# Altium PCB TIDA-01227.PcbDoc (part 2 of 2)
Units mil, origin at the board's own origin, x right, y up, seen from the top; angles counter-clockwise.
Board outline 2300 x 2250 mil, 2 copper layers (Top Layer, Bottom Layer), stack 64.8 mil thick; 107 components, 78 nets, 446 pads, 341 vias.
Unrouted connection lines stored in the file: 1.
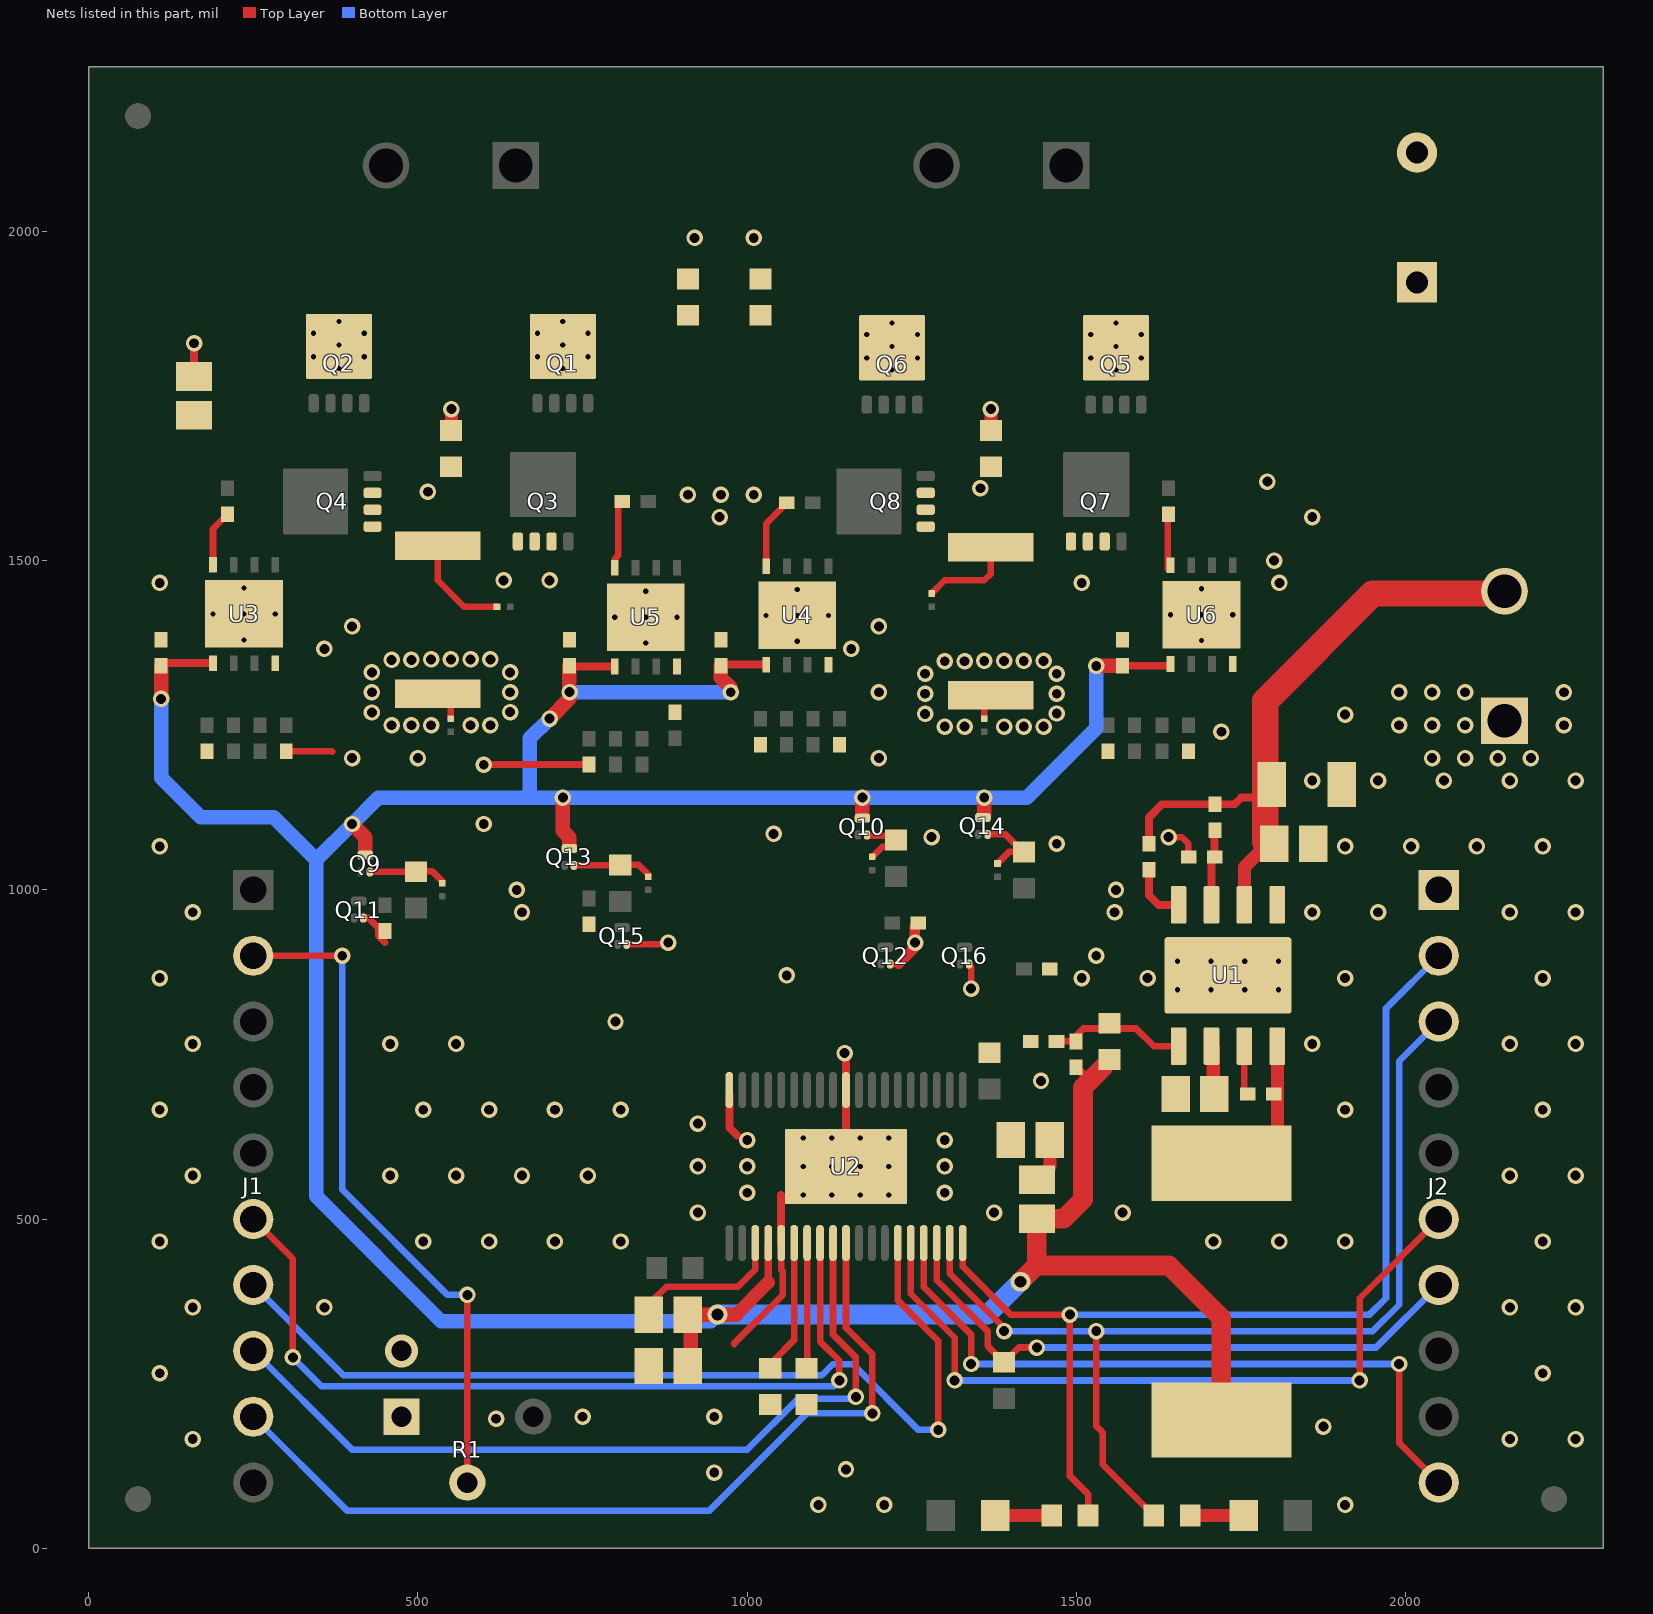
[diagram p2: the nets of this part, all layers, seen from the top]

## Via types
v1: diameter 25, hole 15, Top Layer to Bottom Layer, tented both sides, 241 vias
v2: diameter 19.68, hole 7.87, Top Layer to Bottom Layer, 92 vias
v3: diameter 19.68, hole 7.87, Top Layer to Bottom Layer, tented both sides, 4 vias
v4: diameter 50, hole 31, Top Layer to Bottom Layer, tented both sides, 2 vias
v5: diameter 30, hole 18, Top Layer to Bottom Layer, tented both sides, 2 vias

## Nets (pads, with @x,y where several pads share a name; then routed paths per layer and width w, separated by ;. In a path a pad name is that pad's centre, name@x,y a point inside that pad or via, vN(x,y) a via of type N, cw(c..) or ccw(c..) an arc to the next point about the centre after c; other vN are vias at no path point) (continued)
GND: C1.2 C2.2 C5.2 C6.2 C8.2 C9.2 C10.2 C11.2 C14.2 C17.2 C18.2 C21.2 C22.2 C23.2 C24.2 C25.2 C26.2 J2.1 J4.1 NT2.2 NT4.1 Q11.2 Q12.2 Q15.2 Q16.2 R1.1 R5.1 R6.1 R7.1 R9.1 R12.1 R15.1 R17.1 R19.1 R20.1 R23.1 R24.1 R27.1 R29.1 R31.1 R32.1 R35.1 R36.1 U1.1 U1.9@1730,870 U2.5 U2.29 U2.38 U2.39 U3.4 U3.9 U4.4 U4.9 U5.4 U5.9 U6.4 U6.9 | length 1083.4
  Top Layer w10: R23.1@300,1210.32 369.68,1210.32 370,1210 ; Q11.2@421,957.2 424.86,957.2 440,942.06 440,930 450,920 ; R9.1@530,1297.8 550,1277.8 NT2.2@550,1260 ; v1(600,1190) 600.32,1190.32 R27.1@760,1190.32 ; Q15.2@821,917.2 877.2,917.2 v1(880,920) ; 980,310 980,311.11 1053.89,385 1053.89,421 1051.57,423.32 U2.5@1051.57,463.86 ; v1(1148,752) v1@1150,750 ; 1223,887 1231.49,887 ; v1(1340,850) 1336.89,853.11 1340,856.22 Q16.2@1340,882.12 ; NT4.1@1360,1260 1360,1285.59 R12.1@1370,1295.59 ; v1(1640,1080) 1660,1080 1670,1070 1670,1050.32 R5.1@1670.32,1050
  Top Layer w12: U2.38@972.83,689.25 972.83,639.06 984.65,627.24 ; U2.5@1051.57,463.86 1051.57,536.43 ; U2.39@1150,580 U2.29@1150,689.25 ; U2.29@1150,696.14 v1@1150,750
  Top Layer w16: 1230,887.82 1254.68,912.51 R20.1@1254.68,945
  other v1: 1108,66 1208,66 1908,66 950,115 1150,120 158,166 2158,166 2258,166 1875,185 618.69,196.95 750,200 950,200 108,266 2208,266 158,366 358,366 2158,366 2258,366 108,466 508,466 608,466 708,466 808,466 1708,466 1808,466 1908,466 2208,466 925,510 1375,510 1570,510 1000,540 1300,540 158,566 458,566 558,566 658,566 758,566 2158,566 2258,566 925,580 1000,580 1300,580 1000,620 1300,620 925,645 108,666 508,666 608,666 708,666 808,666 1908,666 2208,666 1446.1,710 158,766 458,766 558,766 1858,766 2158,766 2258,766 800,800 108,866 1508,866 1608,866 1908,866 2208,866 1060,870 1530,900 1255,920 158,966 658,966 1558,966 1858,966 1958,966 2158,966 2258,966 650,1000 1560,1000 108,1066 1908,1066 2008,1066 2108,1066 2208,1066 1470,1070 1280,1080 1040,1085 600,1100 1858,1166 1958,1166 2058,1166 2158,1166 2258,1166 400,1200 500,1200 1200,1200 2040,1200 2090,1200 2140,1200 2190,1200 1720,1240 1300,1247.8 1330,1247.8 1390,1247.8 1420,1247.8 1450,1247.8 460,1250 490,1250 520,1250 580,1250 610,1250 1990,1250 2040,1250 2090,1250 2240,1250 1908,1266 1270,1267.11 1470,1267.8 430,1269.32 640,1270 1270,1297.8 1470,1297.8 430,1300 640,1300 1200,1300 1990,1300 2040,1300 2090,1300 2240,1300 1270,1328.11 1470,1328.11 430,1330.32 640,1330.32 1300,1347.09 1330,1347.09 1360,1347.8 1390,1347.8 1420,1347.8 1450,1347.8 460,1349.29 490,1349.29 520,1350 550,1350 580,1350 610,1350 358,1366 1158,1366 400,1400 1200,1400 108,1466 1508,1466 1808,1466 630,1470 700,1470 1800,1500 958,1566 1858,1566 910,1600 960,1600 1010,1600 514.98,1604.55 1354.08,1609.76 1790,1620
  other v2: 1085.04,536.69 1128.35,536.69 1171.65,536.69 1214.96,536.69 1085.04,580 1128.35,580 1171.65,580 1214.96,580 1085.04,623.31 1128.35,623.31 1171.65,623.31 1214.96,623.31 1704.41,848.35 1755.59,848.35 1704.41,891.65 1755.59,891.65 846,1374.63 1076,1377.43 1690,1378.43 236,1379.63 798.76,1414 846,1414 893.24,1414 1028.76,1416.8 1076,1416.8 1123.24,1416.8 1642.76,1417.8 1690,1417.8 1737.24,1417.8 188.76,1419 236,1419 283.24,1419 846,1453.37 1076,1456.17 1690,1457.17 236,1458.37
  other v3: 1653.23,848.35 1806.77,848.35 1653.23,891.65 1806.77,891.65
  other v4: 475,300
GND_A: NT1.2 Q3.1 Q3.2 Q3.3 Q4.1 Q4.2 Q4.3 R9.2 | length 158.8
  Top Layer w10: R9.2@530,1522.2 530,1470 570,1430 NT1.2@620,1430
GND_B: NT3.1 Q7.1 Q7.2 Q7.3 Q8.1 Q8.2 Q8.3 R12.2 | length 142.4
  Top Layer w10: NT3.1@1280,1450 1300,1470 1360,1470 1370,1480 R12.2@1370,1520
NetC3_1: C3.1 U1.7 | length 74.9
  Top Layer w10: U1.7@1755,762.72 1755,695.32 C3.1@1760.32,690
NetC3_2: C3.2 L1.1 U1.8 | length 144.9
  Top Layer w20: L1.1@1720,584.88 L1.1@1724.88,584.88 ; L1.1@1805,620 U1.8@1805,760
NetC4_2: C4.2 R4.1 R6.2 U1.5 | length 209.7
  Top Layer w10: R6.2@1469.69,770 1498.68,770 R4.1@1499,769.68 1499,778.05 1510.47,789.53 1590.47,789.53 1617.28,762.72 U1.5@1655,762.72
NetC7_2: C7.2 R7.2 | length 78.6
  Top Layer w20: C7.2@1440,559.53 1459.53,579.05 R7.2@1459.53,630
NetC8_1: C8.1 U1.6 | length 73.8
  Top Layer w20: U1.6@1705,762.72 1707.56,760.16 C8.1@1707.56,690
NetC15_2: C15.2 U3.8 | length 85.8
  Top Layer w10: U3.8@188.76,1493.8 188.76,1548.41 188.93,1548.41 C15.2@210.84,1570.31
NetC16_2: C16.2 U4.8 | length 109.3
  Top Layer w10: U4.8@1028.76,1491.6 1028.76,1556.24 C16.2@1060.31,1587.8
NetC19_2: C19.2 U5.8 | length 106
  Top Layer w10: U5.8@798.76,1488.8 798.76,1502.58 804,1507.83 804,1583.69 C19.2@810.31,1590
NetC20_2: C20.2 U6.8 | length 89.6
  Top Layer w10: U6.8@1638.76,1486.6 C20.2@1638.76,1576.24
NetD1_1: D1.1 R11.2 | length 86.1
  Top Layer w20: D1.1@1376.34,50 R11.2@1462.44,50
NetD2_1: D2.1 R10.1 | length 81.1
  Top Layer w20: R10.1@1672.56,50 D2.1@1753.66,50
NetNT5_2: NT5.2 Q9.2 R16.2 | length 114.7
  Top Layer w10: 432,1027.2 496.85,1027.2 R16.2@497.2,1027.56 497.7,1028.05 521.95,1028.05 537.2,1012.8 NT5.2@537.2,1010
NetNT6_2: NT6.2 Q10.2 R18.2 | length 79.6
  Top Layer w10: 1187,1082 R18.2@1220,1082 ; NT6.2@1190,1050 1205.33,1065.33 1215.77,1065.33 R18.2@1226,1075.56
NetNT7_2: NT7.2 Q13.2 R28.2 | length 113.5
  Top Layer w10: 742,1037.21 R28.2@809.65,1037.2 ; R28.2@810.49,1038.05 834.74,1038.05 NT7.2@850,1022.8
NetNT8_2: NT8.2 Q14.2 R30.2 | length 108.3
  Top Layer w10: Q14.2@1369,1084.2 1392.37,1084.2 R30.2@1419.02,1057.56 ; NT8.2@1380,1040 1397.56,1057.56 R30.2@1419.02,1057.56 ; R30.2@1420,1057.56 R30.2@1419.02,1057.56
NetR2_2: R2.2 U1.4 | length 76
  Top Layer w12: R2.2@1610,1030.31 1610,991.73 1624.45,977.28 1641.46,977.28
NetR3_1: R3.1 R5.2 U1.3 | length 104.3
  Top Layer w12: U1.3@1705,977.28 1705,1045.31 R5.2@1709.69,1050 1709.69,1078.82 R3.1@1709.1,1079.41
NFAULT: J2.3 R10.2 U2.18 | length 1562.6
  Top Layer w10: U2.18@1307.48,470.75 1307.48,417.52 1390,335 v1(1390,330) ; v1(1530,330) 1530,185.84 1540,175.84 1540,127.44 R10.2@1617.44,50
  Bottom Layer w10: v1(1390,330) 1950,330 1990,370 1990,740 J2.3@2050,800
NSLEEP: J1.6 U2.8 | length 1314.7
  Top Layer w10: J1.6@250,500 310,440 v1(310,290) ; U2.8@1110.63,470.75 1110.63,314.37 1140,285 v1(1140,255)
  Bottom Layer w10: v1(310,290) 354,246 1131,246 v1(1140,255)
NSTALL: J2.2 R11.1 U2.19 | length 1595.8
  Top Layer w10: U2.19@1327.17,470.75 1327.17,427.83 1400,355 v1(1490,355) 1490,110 1517.56,82.44 R11.1@1517.56,50
  Bottom Layer w10: v1(1490,355) 1945,355 1970,380 1970,820 J2.2@2050,900
POT: J1.2 R1.2 | length 1011.3
  Top Layer w10: J1.2@250,900 v1@375,900 ; R1.2@575,100 v1@575,375
  Bottom Layer w10: v1(385,900) 385,544.92 544.92,385 v1(575,385)
RESET: J1.8 U2.9 | length 1270.4
  Top Layer w10: U2.9@1130.31,475.75 1130.31,324.69 1165,290 v1(1165,230)
  Bottom Layer w10: J1.8@250,300 400,150 1000.11,150 1077.11,227 1162,227 v1(1165,230)
SCLK: J1.7 U2.14 | length 1460.9
  Top Layer w10: U2.14@1228.74,470.75 1228.74,376.26 1290,315 v1(1290,180)
  Bottom Layer w10: J1.7@250,400 387,263 1113.35,263 1129.85,279.5 1160.5,279.5 1260,180 v1(1290,180)
SCS: J2.10 U2.16 | length 1070.4
  Top Layer w10: U2.16@1268.11,470.75 1268.11,396.89 1340,325 v1@1340,285 ; v1(1990,280) 1990,160 J2.10@2050,100
  Bottom Layer w10: v1(1340,280) v1(1990,280)
SDATI: J2.6 U2.15 | length 1153
  Top Layer w10: U2.15@1248.43,470.75 1248.43,386.57 1315,320 v1(1315,255) ; v1(1930,255) 1930,380 J2.6@2050,500
  Bottom Layer w10: v1(1315,255) v1(1930,255)
SDATO: J2.7 R8.1 U2.17 | length 939.2
  Top Layer w10: U2.17@1287.8,470.75 1287.8,407.2 1365,330 1365,307.56 R8.1@1390,282.56 1412.44,305 v1(1440,305)
  Bottom Layer w10: v1(1440,305) 1780,305 1955,305 J2.7@2050,400
STEP/AIN1: J1.9 U2.10 | length 1342.9
  Top Layer w10: U2.10@1150,470.75 1150,335 1190,295 v1(1190,205)
  Bottom Layer w10: J1.9@250,200 393,57 942,57 1090,205 v1(1190,205)
V5: C10.1 U2.6 | length 211.7
  Top Layer w10: C10.1@1041,271.56 1041,286 1071.26,316.26 U2.6@1071.26,463.86 U2.6@1071.26,470.75
V12: C4.1 C7.1 C9.1 C13.2 C17.1 C18.1 C21.1 C22.1 L1.2 Q9.3 Q10.3 Q13.3 Q14.3 R4.2 U2.4 U3.1 U4.1 U5.1 U6.1 | length 5704
  Top Layer w12: C17.1@110,1340.32 113.88,1344.2 U3.1@188.76,1344.2 ; C21.1@730,1340.32 731.12,1339.2 U5.1@798.76,1339.2 ; C18.1@960,1340.32 961.68,1341.99 U4.1@1028.76,1341.99 ; 1031.89,403.89 U2.4@1031.89,463.86 ; R4.2@1500,730.31 1519.84,710.47 1520.47,710.47 ; C22.1@1570,1340.32 1640.08,1340.32 U6.1@1642.76,1342.99
  Top Layer w20: 983,355 1031.89,403.89
  Top Layer w22: v1(110,1290) C17.1@110,1340.32 ; v1(400,1100) 420,1080 419.99,1059.69 ; v1(700,1260) 730,1290 C21.1@730,1340.32 ; v1(720,1140) 720,1090 729.99,1080.01 729.99,1069.7 ; C9.1@918.15,275 914.53,278.62 914.53,355 v5(955,355) 983,355 ; C18.1@960,1340.32 960,1321.72 975,1306.72 v1(975,1300) ; Q10.3@1175,1114.41 v1(1175,1140) ; Q14.3@1360,1114.41 v1(1360,1140) ; v1(1530,1340) 1569.68,1340 C22.1@1570,1340.32
  Top Layer w30: v5(1415,405) 1439.53,429.53 ; C4.1@1540.47,730.47 1520.47,710.47 1510,700 1510,530 1480.47,500.47 C7.1@1440,500.47 1439.53,500 1439.53,429.53 ; L1.2@1720,195.12 1720,350 1640.47,429.53 1439.53,429.53
  Bottom Layer w22: v1(110,1290) 110,1170 170,1110 281,1110 345.5,1045.5 ; v1(700,1260) 670,1230 670,1140 ; v1(730.19,1300.19) 730.39,1300 v1(975,1300) ; v5(955,355) 945,345 535,345 345.5,534.5 345.5,1045.5 ; v1(1530,1340) 1530,1245.65 1424.35,1140 v1(1360,1140) v1(1175,1140) v1(720,1140) 670,1140 ; 345.5,1045.5 v1(400,1100) 440,1140 670,1140
  Bottom Layer w30: v5(955,355) 1365,355 v5(1415,405)
VCP: C13.1 U2.3 | length 244.5
  Top Layer w10: C13.1@855.47,355 855.47,375.47 877.27,397.27 986.16,397.27 1012.2,423.32 U2.3@1012.2,463.86 U2.3@1012.2,470.75
VINT: C11.1 U2.7 | length 197.2
  Top Layer w10: C11.1@1090.94,273.5 U2.7@1090.94,470.75
VM: C1.1 C2.1 C5.1 C6.1 C23.1 C24.1 C25.1 C26.1 J4.2 Q1.5 Q1.6 Q1.7 Q1.8 Q1.9@720,1825.39 Q2.5 Q2.6 Q2.7 Q2.8 Q2.9@380,1825.39 Q5.5 Q5.6 Q5.7 Q5.8 Q5.9@1560,1823.19 Q6.5 Q6.6 Q6.7 Q6.8 Q6.9@1220,1823.19 R2.1 R3.2 U1.2 | length 1102.4
  Top Layer w12: C2.1@160,1777.56 v1@160,1820 ; R2.1@1610,1069.68 1610,1110 1630,1130 1740,1130 1750,1140 1766.85,1140 C5.1@1786.85,1160
  Top Layer w20: C24.1@550.73,1698.29 v1(550.73,1730) ; C26.1@1370,1697.56 v1(1370,1730) ; U1.2@1755,977.28 1755,1034.53 C6.1@1790.47,1070
  Top Layer w40: C6.1@1790.47,1070 1786.85,1073.62 1786.85,1160 1786.85,1286.85 1950,1450 2146.57,1450 J4.2@2150,1453.43
  other v1: 160,1830 920,1990 1010,1990
  other v2: 1220,1789.63 1560,1789.63 380,1791.83 720,1791.83 1181.61,1807.44 1258.39,1807.44 1521.61,1807.44 1598.39,1807.44 341.61,1809.65 418.39,1809.65 681.61,1809.65 758.39,1809.65 1220,1825.26 1560,1825.26 380,1827.46 720,1827.46 1181.61,1843.07 1258.39,1843.07 1521.61,1843.07 1598.39,1843.07 341.61,1845.28 418.39,1845.28 681.61,1845.28 758.39,1845.28 1220,1860.89 1560,1860.89 380,1863.09 720,1863.09
pads on no net: FID1.1 FID2.1 FID3.1 J1.3 J1.4 J1.5 J2.4 J2.5 Q1.9@681.61,1846.26 Q1.9@693.92,1791.83 Q1.9@693.92,1827.46 Q1.9@707.2,1846.26 Q1.9@720,1812.89 Q1.9@732.8,1846.26 Q1.9@746.08,1791.83 Q1.9@746.08,1827.46 Q1.9@758.39,1846.26 Q2.9@341.61,1846.26 Q2.9@353.92,1791.83 Q2.9@353.92,1827.46 Q2.9@367.2,1846.26 Q2.9@380,1812.89 Q2.9@392.8,1846.26 Q2.9@406.08,1791.83 Q2.9@406.08,1827.46 Q2.9@418.39,1846.26 Q3.9@651.61,1636.26 Q3.9@663.92,1581.83 Q3.9@663.92,1617.46 Q3.9@677.2,1636.26 Q3.9@690,1602.89 Q3.9@702.8,1636.26 Q3.9@716.08,1581.83 Q3.9@716.08,1617.46 Q3.9@728.39,1636.26 Q4.9@323.74,1551.61 Q4.9@323.74,1577.2 Q4.9@323.74,1602.8 Q4.9@323.74,1628.39 Q4.9@342.54,1563.92 Q4.9@342.54,1616.08 Q4.9@357.11,1590 Q4.9@378.17,1563.92 Q4.9@378.17,1616.08 Q5.9@1521.61,1844.06 Q5.9@1533.92,1789.63 Q5.9@1533.92,1825.26 Q5.9@1547.2,1844.06 Q5.9@1560,1810.69 Q5.9@1572.8,1844.06 Q5.9@1586.08,1789.63 Q5.9@1586.08,1825.26 Q5.9@1598.39,1844.06 Q6.9@1181.61,1844.06 Q6.9@1193.92,1789.63 Q6.9@1193.92,1825.26 Q6.9@1207.2,1844.06 Q6.9@1220,1810.69 Q6.9@1232.8,1844.06 Q6.9@1246.08,1789.63 Q6.9@1246.08,1825.26 Q6.9@1258.39,1844.06 Q7.9@1491.61,1636.26 Q7.9@1503.92,1581.83 Q7.9@1503.92,1617.46 Q7.9@1517.2,1636.26 Q7.9@1530,1602.89 Q7.9@1542.8,1636.26 Q7.9@1556.08,1581.83 Q7.9@1556.08,1617.46 Q7.9@1568.39,1636.26 Q8.9@1163.74,1551.61 Q8.9@1163.74,1577.2 Q8.9@1163.74,1602.8 Q8.9@1163.74,1628.39 Q8.9@1182.54,1563.92 Q8.9@1182.54,1616.08 Q8.9@1197.11,1590 Q8.9@1218.17,1563.92 Q8.9@1218.17,1616.08 Q9.0 Q10.0 Q11.0 Q12.0 Q13.0 Q14.0 Q15.0 Q16.0 U1.9@1730,870

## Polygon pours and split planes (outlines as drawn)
GND on Bottom Layer "GND_BOT" (solid, remove dead copper, pour order 39): 0,2234.46 2300,2234.46 2300,-15.54 0,-15.54
VM on Bottom Layer "VM_BOT" (solid, remove dead copper, pour order 38): 15.49,2250 15.49,1680 425,1680 1920,1680 1920,1365 1935,1365 2300,1365 2300,2250
GND on Top Layer "GND_TOP" (solid, remove dead copper, pour order 40): 0,2250 2300,2250 2300,0 0,0
AOUT1_MOT on Top Layer "Top Layer-AOUT1_MOT" (solid, remove dead copper, pour order 30): 220,2250 220,1532.8 530,1532.8 530,2250
AOUT2_MOT on Top Layer "Top Layer-AOUT2_MOT" (solid, remove dead copper, pour order 31): 560,2250 560,1560 870,1560 870,2250
BOUT2_MOT on Top Layer "Top Layer-BOUT2_MOT1" (solid, remove dead copper, pour order 32): 1400,2250 1400,1560 1710,1560 1710,2250
BOUT1_MOT on Top Layer "Top Layer-BOUT1_MOT" (solid, remove dead copper, pour order 37): 1060,2250 1060,1532.79 1370,1532.8 1370,2250

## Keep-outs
Keep-Out Layer:
  lines w20: -10,0 ccw(c0,0) 0,-10 ; -10,0 ccw(c0,0) 0,-10 ; -10,0 -10,2250 ; -10,2250 cw(c0,2250) 0,2260 ; -10,2250 cw(c0,2250) 0,2260 ; 0,-10 2300,-10 ; 0,2260 2300,2260 ; 2300,-10 ccw(c2300,0) 2310,0 ; 2300,-10 ccw(c2300,0) 2310,0 ; 2300,2260 cw(c2300,2250) 2310,2250 ; 2300,2260 cw(c2300,2250) 2310,2250 ; 2310,0 2310,2250
  text ".Layer_Name" at 577,-858.49 h60

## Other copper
Top Layer:
  rectangle net VM: 900,1920 1030,2010
  region net GND: 566.26,1657.81 566.19,1657.88 503.31,1657.88 494.25,1648.82 494.25,1590.81
  region net GND: 950.94,731.62 972.83,731.62 972.83,646.89 950.94,646.89
  region net GND_A: 710,1550 710,1500 420,1500 420,1610 440,1610 500,1550
  region net GND_B: 1550,1547.8 1550,1497.8 1260,1497.8 1260,1607.8 1280,1607.8 1340,1547.8
  region net GND: 1440,810 1440,750 1460,730 1430,730 1430,810
  text ".Layer_Name" at 577,-858.49 h60
Bottom Layer:
  text ".Layer_Name" at 577,-858.49 h60

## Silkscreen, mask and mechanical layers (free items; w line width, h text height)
Top Overlay:
  lines w7: 1840,1367 1920,1367 ; 1840,1260 1920,1260 1920,1477 1840,1477 1840,1260
  lines w10: 230,1550 230,1960 310,1960 ; 380,1500 450,1500 ; 610,1500 740,1500 ; 770,1960 1150,1960 ; 950,1500 970,1500 ; 1180,1500 1290,1500 ; 1450,1500 1550,1500 ; 1600,1960 1720,1960 1720,1550
  text ".PRJ_Number" at 790,2180 h30
  text "Rev." at 790,2130 h30
  text ".PCB_Rev" at 930,2130 h30
  text "High Voltage Stepper" at 780,1980 h30
  text "A1" at 254,1900 h40
  text "A2" at 789,1900 h40
  text "B1" at 1100,1900 h40
  text "B2" at 1630,1900 h40
  text "VM" at 1860,1457 h30 r270
  text "GND" at 1860,1357 h30 r270
  text "GND-STL-FLT" at 1955,1050 h28 r270
  text "3.3-POT" at 319.51,1047.48 h28 r270
  text "DRV8711" at 660,760 h60
  text "SLP-CLK-RST-STP-DIR" at 320,555 h28 r270
  text "SDI-SDO-B1-B2-SCS" at 2115,525 h28 r270
  text "STALL" at 1230,100 h30
  text "FAULT" at 1710,100 h30
  text ".Layer_Name" at 577,-858.49 h60
Bottom Overlay:
  text ".Layer_Name" at 577,-858.49 h60
Top Paste:
  text ".Layer_Name" at 577,-858.49 h60
Bottom Paste:
  text ".Layer_Name" at 577,-858.49 h60
Top Solder:
  text ".Layer_Name" at 577,-858.49 h60
  text ".Layer_Name" at 577,-858.49 h60
Bottom Solder:
  text ".Layer_Name" at 577,-858.49 h60
Drill Guide:
  text ".Layer_Name" at 577,-858.49 h60
M1 Board Outline:
  the board outline again, w10
  text ".Layer_Name" at 577,-858.49 h60
M2 Board Dimensions:
  rectangle: -0.5,-285.5 124.5,-160.5
  rectangle: 124.5,-410.5 499.5,-285.5
  lines w7: -0.5,-285.5 999.5,-285.5 ; 124.5,-410.5 124.5,-160.5 ; 249.5,-410.5 249.5,-160.5 ; 499.5,-410.5 499.5,-160.5 ; 749.5,-410.5 749.5,-160.5 ; -0.5,-410.5 999.5,-410.5 999.5,-160.5 -0.5,-160.5 -0.5,-410.5
  lines w10: -0.5,-475.5 -0.5,-455.5 ; 59.5,-485.5 -0.5,-465.5 ; 59.5,-445.5 -0.5,-465.5 ; 223.58,-465.5 -0.5,-465.5 ; 775.42,-465.5 999.5,-465.5 ; 939.5,-485.5 999.5,-465.5 ; 939.5,-445.5 999.5,-465.5 ; 999.5,-475.5 999.5,-455.5
  text "1000 (mil)" at 233.58,-501.49 h60
  text ".Layer_Name" at 577,-858.49 h60
M3 3D STEP Top:
  text ".Layer_Name" at 577,-858.49 h60
M4 3D STEP Bottom:
  text ".Layer_Name" at 577,-858.49 h60
M5 Assembly Top:
  lines w10: -292,-930.17 6308,-930.17 ; -292,-726.83 6310,-726.83 ; -292,-523.5 -292,-1133.5 3713,-1133.5 6310,-1133.5 6310,-523.5 -291.5,-523.5 -291.5,-1133.5 1284,-1133.5 ; 2173,-1133.5 2173,-523.5 ; 3440,-726.83 3440,-523.5 ; 4280,-726.83 4280,-523.5 ; 4902,-1140 4902,-937.17
  text "COMPONENTS MARKED 'DNP' SHOULD NOT BE POPULATED." at 1153.5,-318.5 h60
  text "ASSEMBLY VARIANT:" at 1153,-434 h60
  text ".VariantName" at 2189,-434 h60
  text "PCB VIEWED FROM TOP SIDE" at -228.5,-655.67 h60
  text "BOARD #:" at 2248,-655.67 h60
  text ".PRJ_Number" at 2793.5,-655.67 h60
  text "REV:" at 3638,-655.67 h60
  text ".PCB_Rev" at 3929.5,-655.67 h60
  text "SVN REV:" at 4476,-655.67 h60
  text ".VersionControl_RevNumber" at 4982,-655.67 h60
  text "IGNORE ->" at -228.5,-858.49 h60
  text "PLOT NAME =" at -228.5,-1064.34 h60
  text ".plot_File_Name" at 577,-1064.34 h60
  text "GENERATED    :" at 2250,-1064.34 h60
  text ".Print_Date" at 3119.5,-1064.34 h60
  text ".Print_Time" at 3848.5,-1064.34 h60
  text "TEXAS INSTRUMENTS" at 5113,-1064.34 h60
M6 Assembly Bottom:
  lines w10: -292.5,-727.33 6309.5,-727.33 ; -290.5,-930.67 6309.5,-930.67 ; 1115.5,-1140.5 1115.5,-937.67 ; 1737.5,-727.33 1737.5,-524 ; 2577.5,-727.33 2577.5,-524 ; 3844.5,-1134 3844.5,-524 ; 4733.5,-1134 6309,-1134 6309,-524 -292.5,-524 -292.5,-1134 2304.5,-1134 6309.5,-1134 6309.5,-524
  text "COMPONENTS MARKED 'DNP' SHOULD NOT BE POPULATED." at 6102,-318 h60
  text ".VariantName" at 5058,-434 h60
  text "ASSEMBLY VARIANT:" at 6097,-434 h60
  text ".VersionControl_RevNumber" at 1035.5,-656.17 h60
  text "SVN REV:" at 1541.5,-656.17 h60
  text ".PCB_Rev" at 2088,-656.17 h60
  text "REV:" at 2379.5,-656.17 h60
  text ".PRJ_Number" at 3224,-656.17 h60
  text "BOARD #:" at 3769.5,-656.17 h60
  text "PCB VIEWED FROM BOTTOM SIDE" at 6246,-656.17 h60
  text "IGNORE ->" at 2547.85,-858.49 h60
  text "TEXAS INSTRUMENTS" at 904.5,-1064.84 h60
  text ".Print_Time" at 2169,-1064.84 h60
  text ".Print_Date" at 2898,-1064.84 h60
  text "GENERATED    :" at 3767.5,-1064.84 h60
  text ".plot_File_Name" at 5440.5,-1064.84 h60
  text "PLOT NAME =" at 6246,-1064.84 h60
M9 Title Sheet:
  drawing of 57 lines, arcs and shapes, not listed
  text "1" at 739.84,8036.5 h70
  text "2" at 3235.5,8036.5 h70
  text "3" at 5724.84,8036.5 h70
  text "4" at 8231.51,8036.5 h70
  text "5" at 10730.5,8036.5 h70
  text "6" at 13235.5,8036.5 h70
  text "A" at -416.5,6893.5 h70
  text "A" at 14383.5,6893.5 h70
  text "B" at -416.5,4513.5 h70
  text "B" at 14383.5,4513.5 h70
  text "C" at -416.5,2138.5 h70
  text "C" at 14383.5,2138.5 h70
  text "PROJECT TITLE:" at 11343.5,277.5 h45
  text ".PRJ_Title" at 11393.5,144.17 h70
  text "DESIGNED FOR:" at 11343.5,-23.5 h45
  text ".PRJ_Customer" at 11393.5,-163.5 h70
  text "D" at -416.5,-231.5 h70
  text "D" at 14383.5,-231.5 h70
  text "FILE NAME:" at 11343.5,-323.5 h45
  text ".PCB_File_Name_No_Path" at 11393.5,-443.5 h70
  text "Texas Instruments (TI) and/or its licensors do not warrant the accuracy or completeness of this specification" at 6374,-605.34 h45
  text "ENGINEER:" at 11343.5,-613.5 h45
  text "LAYOUT BY:" at 12848.5,-613.5 h45
  text "or any information contained therein. TI and/or its licensors do not warrant that this design will meet" at 6329.01,-718 h45
  text ".PRJ_Engineer" at 11393.5,-768.49 h70
  text ".PCB_Layout" at 12899,-768.49 h70
  text "the specifications, will be suitable for your application or fit for any particular purpose, or will operate in" at 6329.01,-830.67 h45
  text ".Layer_Name" at 577,-858.49 h60
  text "ALTIUM DESIGNER VERSION:" at 12848.5,-923.5 h45
  text "an implementation. TI and/or its licensors do not warrant that the design is production worthy. You should" at 6329.01,-943.33 h45
  text "completely validate and test your design implementation to confirm the system functionality for your application." at 6374,-1056 h45
  text ".print_Scale" at 11393.5,-1056.83 h70
  text ".Application_BuildNumber" at 12899,-1056.83 h70
  text "1" at 739.84,-1263.5 h70
  text "2" at 3235.5,-1263.5 h70
  text "3" at 5724.84,-1263.5 h70
  text "4" at 8231.51,-1263.5 h70
  text "5" at 10730.5,-1263.5 h70
  text "6" at 13235.5,-1263.5 h70
M10 Fab Notes:
  drawing of 189 lines, arcs and shapes, not listed
  text "DESIGN INFORMATION" at 12381.52,6022 h60
  text "MIN. TRACK WIDTH:" at 11736.96,5842 h60
  text "10" at 12833.2,5842 h60
  text "MIL" at 12987.96,5842 h60
  text "MIN. CLEARANCE:" at 11736.96,5710 h60
  text "0.2" at 12773.2,5710 h60
  text "mm" at 12987.96,5710 h60
  text "MIN. VIA PAD SIZE:" at 11736.96,5578 h60
  text "24" at 12803.21,5578 h60
  text "MIL" at 12987.96,5578 h60
  text "0.05mm (2MIL)" at 12431.96,5436.29 h60
  text "MINIMUM ANNULAR RING" at 11407.73,5432 h60
  text "EXTERNAL" at 13139.96,5432 h60
  text "PER" at 11607.73,5314 h60
  text "IPC-D-275 CLASS 2 LEVEL C" at 11827.73,5314 h60
  text "MIL, HOLES" at 13315.96,5201.71 h60
  text "+/-" at 12923.5,5201 h60
  text "+/-" at 13777.5,5201 h60
  text "REGISTRATION TOLERANCES:" at 11407.73,5196 h60
  text "METAL" at 12607.5,5196 h60
  text "5" at 13183.7,5196 h60
  text "3" at 14016.7,5196 h60
  text "MIL" at 14132.96,5196 h60
  text "+/-" at 13777.5,5083 h60
  text "HOLE SIZE TOLERANCE (UNLESS OTHERWISE SPECIFIED):" at 11407.73,5078 h60
  text "3" at 14016.7,5078 h60
  text "MIL" at 14132.96,5078 h60
  text "MATERIAL:" at 11332.96,4868.54 h60
  text "FR-4 High Tg" at 12319.4,4728.21 h60
  text "FR-408" at 11753.96,4719.64 h60
  text "OTHER" at 13241.96,4719.64 h60
  text "X" at 12164.5,4716 h60
  text "62 MIL (1.6mm) +/-10%" at 12074.06,4556.92 h60
  text "THICKNESS:" at 11407.73,4552.64 h60
  text "X" at 11945.9,4552.64 h60
  text "OTHER" at 13358.96,4552.64 h60
  text "TOLERANCE:" at 11407.73,4394.64 h60
  text "X" at 12247.03,4394.64 h60
  text "ANSI IPC-6012 TYPE 3 CLASS 2" at 12433.98,4394.64 h60
  text "OTHER +/-" at 12433.96,4238.64 h60
  text "BOW & TWIST:" at 11407.73,4081.64 h60
  text "X" at 12247.03,4081.64 h60
  text "ANSI IPC-6012 TYPE 3 CLASS 2" at 12433.98,4081.64 h60
  text "OTHER +/-" at 12433.96,3923.13 h60
  text "DRILLING:" at 11332.96,3784.64 h60
  text "REFERENCE:" at 11407.73,3667.64 h60
  text "X" at 12055.96,3667.64 h60
  text "AS SHOWN" at 12242.96,3667.64 h60
  text "X" at 12956.96,3667.64 h60
  text "NC_DRILL FILES" at 13093.96,3667.64 h60
  text "PTH MIN COPPER THICKNESS:" at 11407.73,3509.64 h60
  text "X" at 12757.96,3509.64 h60
  text "1MIL" at 12894.96,3509.64 h60
  text "OTHER" at 13391.96,3509.64 h60
  text "BOARD FINISH:" at 11332.96,3350.64 h60
  text "SILKSCREEN:" at 11488.18,3232.64 h60
  text "X" at 12436.96,3232.64 h60
  text "TOP" at 12562.96,3232.64 h60
  text "BOTTOM" at 13073.96,3232.64 h60
  text "SILKSCREEN COLOR:" at 11488.18,3065.64 h60
  text "X" at 12435.92,3065.64 h60
  text "WHITE" at 12562.96,3065.64 h60
  text "OTHER" at 13073.96,3065.64 h60
  text "RED" at 13673.96,2910.64 h60
  text "X" at 13160,2910 h60
  text "GREEN" at 12693.96,2906.44 h60
  text "OTHER" at 13311.96,2906.44 h60
  text "SOLDER RESIST COLOR:" at 11488.18,2895.64 h60
  text "X" at 12566.92,2736.44 h60
  text "MATTE" at 12693.96,2736.44 h60
  text "SEMI-GLOSS" at 13311.5,2735.8 h60
  text "IMMERSION GOLD (ENIG)" at 12393.96,2547.92 h60
  text "ENEPIG" at 13731.5,2544.64 h60
  text "SURFACE FINISH:" at 11332.96,2543.64 h60
  text "X" at 12207.01,2543.64 h60
  text "IMM. TIN/SILVER OR EQUIV" at 11662.5,2386.64 h60
  text "OTHER" at 13093.96,2386.64 h60
  text "ARRAY/PANEL:" at 11332.96,2207.64 h60
  text "CUT AND TRIM PER M1 BOARD OUTLINE" at 12393.96,2203.35 h60
  text "N.C. ROUTE" at 12393.96,2051.64 h60
  text "X" at 13072.96,2051.64 h60
  text "V. SCORE" at 13259.96,2051.64 h60
  text "CERTIFICATION:" at 11332.96,1914.64 h60
  text "MATERIALS AND WORKMANSHIP FOR ALL PCBS" at 12057.96,1914.64 h60
  text "TO MEET OR EXCEED THE REQUIREMENTS OF:" at 12057.96,1816.64 h60
  text "X" at 11684.46,1680.13 h60
  text "ANSI IPC-A-600F CLASS ->" at 11823.46,1680.13 h60
  text "X" at 13462.52,1680.13 h60
  text "2" at 13581.46,1680.14 h60
  text "1" at 13266.46,1678.64 h60
  text "3" at 13935.46,1678.64 h60
  text "X" at 11686.52,1520.64 h60
  text "UL 94V-0" at 11823.46,1520.64 h60
  text "X" at 12498.52,1520.64 h60
  text "RoHS" at 12635.46,1520.64 h60
  text "OTHER" at 13279.86,1520.64 h60
  text "PER ORDER" at 13676.92,1520.64 h60
  text "ADDITIONAL REQUIREMENTS:" at 11332.96,1379.64 h60
  text "MICROSECTION:" at 11407.73,1264.64 h60
  text "YES" at 12313.46,1264.64 h60
  text "REQUIRED" at 13174.96,1108.49 h60
  text "BARE BOARD ELEC. TEST:" at 11407.73,1105.64 h60
  text "NONE" at 12713.46,1105.64 h60
  text "X" at 13047.96,1105.64 h60
  text "PER ORDER" at 13766.96,1105.64 h60
  text "MANUFACTURER'S UL:" at 11407.73,948.64 h60
  text "RAIL" at 12573.46,944.35 h60
  text "METAL" at 13065.27,944.35 h60
  text "X" at 13440.5,944 h60
  text "SILK" at 13576.96,944.35 h60
  text ".Layer_Name" at 577,-858.49 h60
M11 Gerber Information:
  lines w10: -292,-930.17 6308,-930.17 ; -292,-726.83 6310,-726.83 ; -292,-523.5 -292,-1133.5 3713,-1133.5 6310,-1133.5 6310,-523.5 -291.5,-523.5 -291.5,-1133.5 1284,-1133.5 ; 2173,-1133.5 2173,-523.5 ; 3440,-726.83 3440,-523.5 ; 4280,-726.83 4280,-523.5 ; 4902,-1140 4902,-937.17
  text "ALL ARTWORK VIEWED FROM TOP SIDE" at -228.5,-655.67 h60
  text "BOARD #:" at 2248,-655.67 h60
  text ".PRJ_Number" at 2793.5,-655.67 h60
  text "REV:" at 3638,-655.67 h60
  text ".PCB_Rev" at 3929.5,-655.67 h60
  text "SVN REV:" at 4476,-655.67 h60
  text ".VersionControl_RevNumber" at 4982,-655.67 h60
  text "LAYER NAME =" at -228.5,-858.49 h60
  text "PLOT NAME =" at -228.5,-1064.34 h60
  text ".plot_File_Name" at 577,-1064.34 h60
  text "GENERATED    :" at 2250,-1064.34 h60
  text ".Print_Date" at 3119.5,-1064.34 h60
  text ".Print_Time" at 3848.5,-1064.34 h60
  text "TEXAS INSTRUMENTS" at 5113,-1064.34 h60
M12 Stackup:
  drawing of 165 lines, arcs and shapes, not listed
  text "Layer" at 9850.55,7840 h60
  text "Name" at 10260.47,7840 h60
  text "Material" at 11120.23,7840 h60
  text "Thickness" at 11980,7840 h60
  text "Constant" at 12629.84,7840 h60
  text "Board Layer Stack" at 13199.7,7840 h60
  text "1" at 9850.55,7720 h60
  text "Top Overlay" at 10260.47,7720 h60
  text "2" at 9850.55,7600 h60
  text "Top Solder" at 10260.47,7600 h60
  text "Solder Resist" at 11120.23,7600 h60
  text "0.40mil" at 11980,7600 h60
  text "3.5" at 12629.84,7600 h60
  text "3" at 9850.55,7480 h60
  text "Top Layer" at 10260.47,7480 h60
  text "Copper" at 11120.23,7480 h60
  text "2.80mil" at 11980,7480 h60
  text "4" at 9850.55,7360 h60
  text "Dielectric1" at 10260.47,7360 h60
  text "FR-4" at 11120.23,7360 h60
  text "59.20mil" at 11980,7360 h60
  text "4.8" at 12629.84,7360 h60
  text "5" at 9850.55,7240 h60
  text "Bottom Layer" at 10260.47,7240 h60
  text "Copper" at 11120.23,7240 h60
  text "2.80mil" at 11980,7240 h60
  text "6" at 9850.55,7120 h60
  text "Bottom Solder" at 10260.47,7120 h60
  text "Solder Resist" at 11120.23,7120 h60
  text "0.40mil" at 11980,7120 h60
  text "3.5" at 12629.84,7120 h60
  text ".Layer_Name" at 577,-858.49 h60
M13 Component Bodies Top:
  text ".Layer_Name" at 577,-858.49 h60
M14 Component Bodies Bottom:
  text ".Layer_Name" at 577,-858.49 h60
M15 Courtyards Top:
  text ".Layer_Name" at 577,-858.49 h60
M16 Courtyards Bottom:
  text ".Layer_Name" at 577,-858.49 h60
Drill Drawing:
  lines w10: 2986.7,1514.24 3008.8,1525.28 3030.89,1514.24 3019.84,1536.34 3030.89,1558.43 3008.8,1547.39 2986.7,1558.43 2997.74,1536.34 2986.7,1514.24 ; 2986.7,1624.74 2997.74,1624.74 3008.8,1613.68 3019.84,1624.74 3030.89,1624.74 3019.84,1635.78 3030.89,1646.84 3019.84,1646.84 3008.8,1657.89 2997.74,1646.84 2986.7,1646.84 2997.74,1635.78 2986.7,1624.74 ; 2986.7,1856.78 3030.89,1856.78 3008.8,1812.59 2986.7,1856.78 ; 2986.7,2022.53 2997.74,2022.53 2997.74,2011.49 3019.84,2011.49 3019.84,2022.53 3030.89,2022.53 3030.89,2044.64 3019.84,2044.64 3019.84,2055.68 2997.74,2055.68 2997.74,2044.64 2986.7,2044.64 2986.7,2022.53 ; 2986.7,2110.93 2986.7,2121.99 2997.74,2133.03 2986.7,2144.09 2986.7,2155.14 2997.74,2155.14 3008.8,2144.09 3019.84,2155.14 3030.89,2155.14 3030.89,2144.09 3019.84,2133.03 3030.89,2121.99 3030.89,2110.93 3019.84,2110.93 3008.8,2121.99 2997.74,2110.93 2986.7,2110.93 ; 2995.53,1523.07 3008.8,1529.7 3022.05,1523.07 3015.43,1536.34 3022.05,1549.59 3008.8,1542.97 2995.53,1549.59 3002.16,1536.34 2995.53,1523.07 ; 2995.53,1629.16 3002.16,1629.16 3008.8,1622.53 3015.43,1629.16 3022.05,1629.16 3015.43,1635.78 3022.05,1642.41 3015.43,1642.41 3008.8,1649.05 3002.16,1642.41 2995.53,1642.41 3002.16,1635.78 2995.53,1629.16 ; 2995.53,1847.95 3022.05,1847.95 3008.8,1821.43 2995.53,1847.95 ; 2995.53,2026.95 3002.16,2026.95 3002.16,2020.32 3015.43,2020.32 3015.43,2026.95 3022.05,2026.95 3022.05,2040.22 3015.43,2040.22 3015.43,2046.84 3002.16,2046.84 3002.16,2040.22 2995.53,2040.22 2995.53,2026.95 ; 2995.53,2119.78 2995.53,2126.41 3002.16,2133.03 2995.53,2139.66 2995.53,2146.3 3002.16,2146.3 3008.8,2139.66 3015.43,2146.3 3022.05,2146.3 3022.05,2139.66 3015.43,2133.03 3022.05,2126.41 3022.05,2119.78 3015.43,2119.78 3008.8,2126.41 3002.16,2119.78 2995.53,2119.78
  lines w12: 2946,1484.4 4835.36,1484.4 ; 2946,2180.55 4835.36,2180.55 ; 3261.66,1384.95 3261.66,2280 ; 3578.77,1384.95 3578.77,2280 ; 4200.77,1384.95 4200.77,2280 ; 4445.12,1384.95 4445.12,2280 ; 2946,1384.95 4835.36,1384.95 4835.36,2280 2946,2280 2946,1384.95
  text "Symbol" at 3005.67,2210.39 h72
  text "Quantity" at 3291.5,2210.39 h72
  text "Finished Hole Size" at 3608.6,2210.39 h72
  text "Plated" at 4230.6,2210.39 h72
  text "Hole Type" at 4474.95,2210.39 h72
  text "96" at 3291.5,2110.93 h60
  text "7.87mil (0.200mm)" at 3608.6,2110.93 h60
  text "PTH" at 4230.6,2110.93 h60
  text "Round" at 4474.95,2110.93 h60
  text "241" at 3291.5,2011.49 h60
  text "15.00mil (0.381mm)" at 3608.6,2011.49 h60
  text "PTH" at 4230.6,2011.49 h60
  text "Round" at 4474.95,2011.49 h60
  text "2" at 3291.5,1912.03 h60
  text "18.00mil (0.457mm)" at 3608.6,1912.03 h60
  text "PTH" at 4230.6,1912.03 h60
  text "Round" at 4474.95,1912.03 h60
  text "A" at 2984.07,1902.04 h44.2
  text "5" at 3291.5,1812.59 h60
  text "31.00mil (0.787mm)" at 3608.6,1812.59 h60
  text "PTH" at 4230.6,1812.59 h60
  text "Round" at 4474.95,1812.59 h60
  text "2" at 3291.5,1713.14 h60
  text "33.46mil (0.850mm)" at 3608.6,1713.14 h60
  text "PTH" at 4230.6,1713.14 h60
  text "Round" at 4474.95,1713.14 h60
  text "C" at 2984.07,1703.14 h44.2
  text "20" at 3291.5,1613.68 h60
  text "40.16mil (1.020mm)" at 3608.6,1613.68 h60
  text "PTH" at 4230.6,1613.68 h60
  text "Round" at 4474.95,1613.68 h60
  text "6" at 3291.5,1514.24 h60
  text "51.18mil (1.300mm)" at 3608.6,1514.24 h60
  text "PTH" at 4230.6,1514.24 h60
  text "Round" at 4474.95,1514.24 h60
  text "372 Total" at 3291.5,1414.78 h60
  text ".Layer_Name" at 577,-858.49 h60

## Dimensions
0,0 to 0,2250 on M2 Board Dimensions
0,0 to 2300,0 on M2 Board Dimensions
